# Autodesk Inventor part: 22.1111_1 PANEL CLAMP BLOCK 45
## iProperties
Created: 2008-12
Part Number: 22.1111_1 PANEL CLAMP BLOCK 45
Document SubType Name: Modeling
Designer: Administrator
Density: 1.06 g/cm^3
Material: ABS Plastic
Mass: 1.90542 g
Surface Area: 19.0167 cm^2
Volume: 1.79757 cm^3
Author: Administrator
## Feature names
1. Base1
